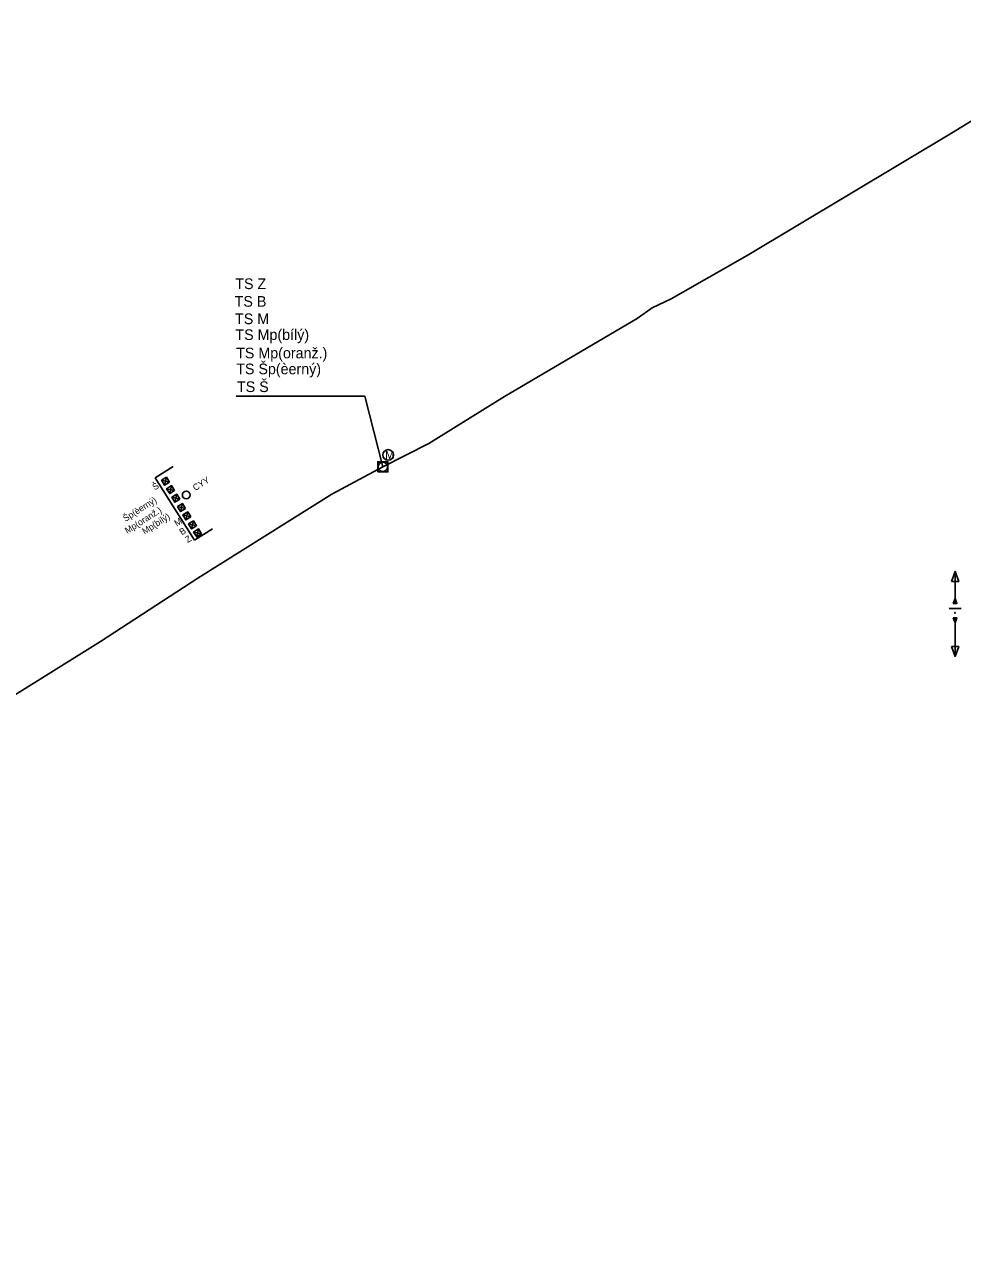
# Model space of a CAD drawing. Extents: x -566419 to -564928, y -1204142 to -1203285.
# Drawn here: x -565891.9 to -565716, y -1203782.2 to -1203552.9 of the extents above; entities that cross this region are included whole.
import ezdxf

# ---------------------------------------------------------------- set-up
doc = ezdxf.new("R2010")
doc.units = 0
for name, color, linetype in [('Trasa DialT', 7, 'Continuous'), ('Vrstva 10', 7, 'Continuous'), ('Vrstva 14', 7, 'Continuous'), ('Vrstva 58', 7, 'Continuous'), ('Vrstva 59', 7, 'Continuous')]:
    doc.layers.add(name, color=color, linetype=linetype)

msp = doc.modelspace()

# ---------------------------------------------------------------- linework, layer by layer
at = {"layer": 'Trasa DialT'}
msp.add_lwpolyline([(-566073.67, -1203782.22), (-566056.63, -1203772.53), (-566043, -1203764.09), (-566015.62, -1203747.88), (-566012.37, -1203746.46), (-566010.84, -1203745.83), (-565982.47, -1203730.93), (-565959.02, -1203717.35), (-565949.23, -1203710.68), (-565941.14, -1203704.76), (-565925.02, -1203697.44), (-565902.62, -1203684.17), (-565877.66, -1203668.62), (-565859.39, -1203656.71), (-565834.25, -1203640.96), (-565824.71, -1203635.85), (-565816.09, -1203631.46), (-565801.91, -1203622.65), (-565777.04, -1203608.03), (-565774.24, -1203606.03), (-565770.67, -1203604.37), (-565756.39, -1203596.24), (-565718.08, -1203573.28), (-565684.87, -1203552.9)], dxfattribs=at)
at = {"layer": 'Vrstva 10'}
for p, q in [((-565867.39, -1203637.93), (-565864.01, -1203635.79)), ((-565860.01, -1203649.59), (-565867.39, -1203637.93)), ((-565864.69, -1203638.7), (-565866.2, -1203638.36)), ((-565865.62, -1203639.28), (-565865.28, -1203637.78)), ((-565863.74, -1203640.29), (-565865.24, -1203639.95)), ((-565864.66, -1203640.87), (-565864.32, -1203639.37)), ((-565863.68, -1203642.49), (-565863.34, -1203640.98)), ((-565862.76, -1203641.9), (-565864.26, -1203641.56)), ((-565861.7, -1203643.65), (-565863.2, -1203643.31)), ((-565862.62, -1203644.23), (-565862.28, -1203642.73)), ((-565860.71, -1203645.21), (-565862.21, -1203644.87)), ((-565861.63, -1203645.79), (-565861.29, -1203644.29)), ((-565859.64, -1203646.9), (-565861.14, -1203646.56)), ((-565860.56, -1203647.49), (-565860.22, -1203645.98)), ((-565856.63, -1203647.45), (-565860.01, -1203649.59)), ((-565859.61, -1203648.99), (-565859.27, -1203647.48)), ((-565858.69, -1203648.41), (-565860.19, -1203648.07))]:
    msp.add_line(p, q, dxfattribs=at)
for points in [[(-565864.69, -1203638.7), (-565865.28, -1203637.78), (-565866.2, -1203638.36), (-565865.62, -1203639.28)], [(-565863.74, -1203640.29), (-565864.32, -1203639.37), (-565865.24, -1203639.95), (-565864.66, -1203640.87)], [(-565862.76, -1203641.9), (-565863.34, -1203640.98), (-565864.26, -1203641.56), (-565863.68, -1203642.49)], [(-565861.7, -1203643.65), (-565862.28, -1203642.73), (-565863.2, -1203643.31), (-565862.62, -1203644.23)], [(-565860.71, -1203645.21), (-565861.29, -1203644.29), (-565862.21, -1203644.87), (-565861.63, -1203645.79)], [(-565859.64, -1203646.9), (-565860.22, -1203645.98), (-565861.14, -1203646.56), (-565860.56, -1203647.49)], [(-565858.69, -1203648.41), (-565859.27, -1203647.48), (-565860.19, -1203648.07), (-565859.61, -1203648.99)]]:
    msp.add_lwpolyline(points, close=True, dxfattribs=at)
msp.add_circle((-565861.57, -1203641.11), 0.726, dxfattribs=at)
at = {"layer": 'Vrstva 14'}
msp.add_lwpolyline([(-565824.71, -1203635.85), (-565828.1, -1203622.58), (-565852.21, -1203622.58)], dxfattribs=at)
msp.add_lwpolyline([(-565825.67, -1203636.81), (-565823.75, -1203636.81), (-565823.75, -1203634.89), (-565825.67, -1203634.89)], close=True, dxfattribs=at)
msp.add_circle((-565824.71, -1203635.85), 0.864, dxfattribs=at)
at = {"layer": 'Vrstva 58'}
for p, q in [((-565717.44, -1203661.45), (-565717.44, -1203655.45)), ((-565718.56, -1203662.39), (-565716.31, -1203662.39)), ((-565717.44, -1203671.39), (-565717.44, -1203664.16))]:
    msp.add_line(p, q, dxfattribs=at)
for points in [[(-565718.12, -1203657.33), (-565717.44, -1203655.45), (-565716.75, -1203657.33)], [(-565717.78, -1203661.45), (-565717.44, -1203660.51), (-565717.09, -1203661.45)], [(-565717.78, -1203664.16), (-565717.09, -1203664.16), (-565717.44, -1203665.1)], [(-565718.12, -1203669.51), (-565717.44, -1203671.39), (-565716.75, -1203669.51)]]:
    msp.add_lwpolyline(points, close=True, dxfattribs=at)
msp.add_circle((-565717.44, -1203663.22), 0.075, dxfattribs=at)
at = {"layer": 'Vrstva 59'}
msp.add_circle((-565823.72, -1203633.62), 1, dxfattribs=at)

# ---------------------------------------------------------------- texts
at = {"layer": 'Vrstva 10'}
for s, p in [('Š', (-565867.46, -1203640.28)), ('CYY', (-565859.87, -1203640.4)), ('Šp(èerný)', (-565872.94, -1203646.16)), ('Mp(oranž.)', (-565872.61, -1203648.43)), ('Mp(bílý)', (-565869.37, -1203648.55)), ('M', (-565863.33, -1203647.06)), ('B', (-565862.39, -1203648.7)), ('Z', (-565861.3, -1203650.15))]:
    msp.add_text(s, height=1.2, rotation=32.3288, dxfattribs=at).set_placement(p)
at = {"layer": 'Vrstva 14'}
for s, p in [('TS Z', (-565852.37, -1203602.52)), ('TS B', (-565852.49, -1203605.82)), ('TS M', (-565852.41, -1203609.09)), ('TS Mp(bílý)', (-565852.35, -1203612.06)), ('TS Mp(oranž.)', (-565852.21, -1203615.5)), ('TS Šp(èerný)', (-565852.2, -1203618.48)), ('TS Š', (-565852.05, -1203621.82))]:
    msp.add_text(s, height=2, dxfattribs=at).set_placement(p)
at = {"layer": 'Vrstva 59'}
msp.add_text('M', height=1.5, dxfattribs=at).set_placement((-565824.27, -1203634.37))

doc.saveas('drawing.dxf')
